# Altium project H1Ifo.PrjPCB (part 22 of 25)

## Sheet IfoEndY3.SchDoc: D1800185
size C; Engineer: Daniel Sigg; DocumentNumber: 7; Revision: 4; SheetNumber: 7; SheetTotal: 8
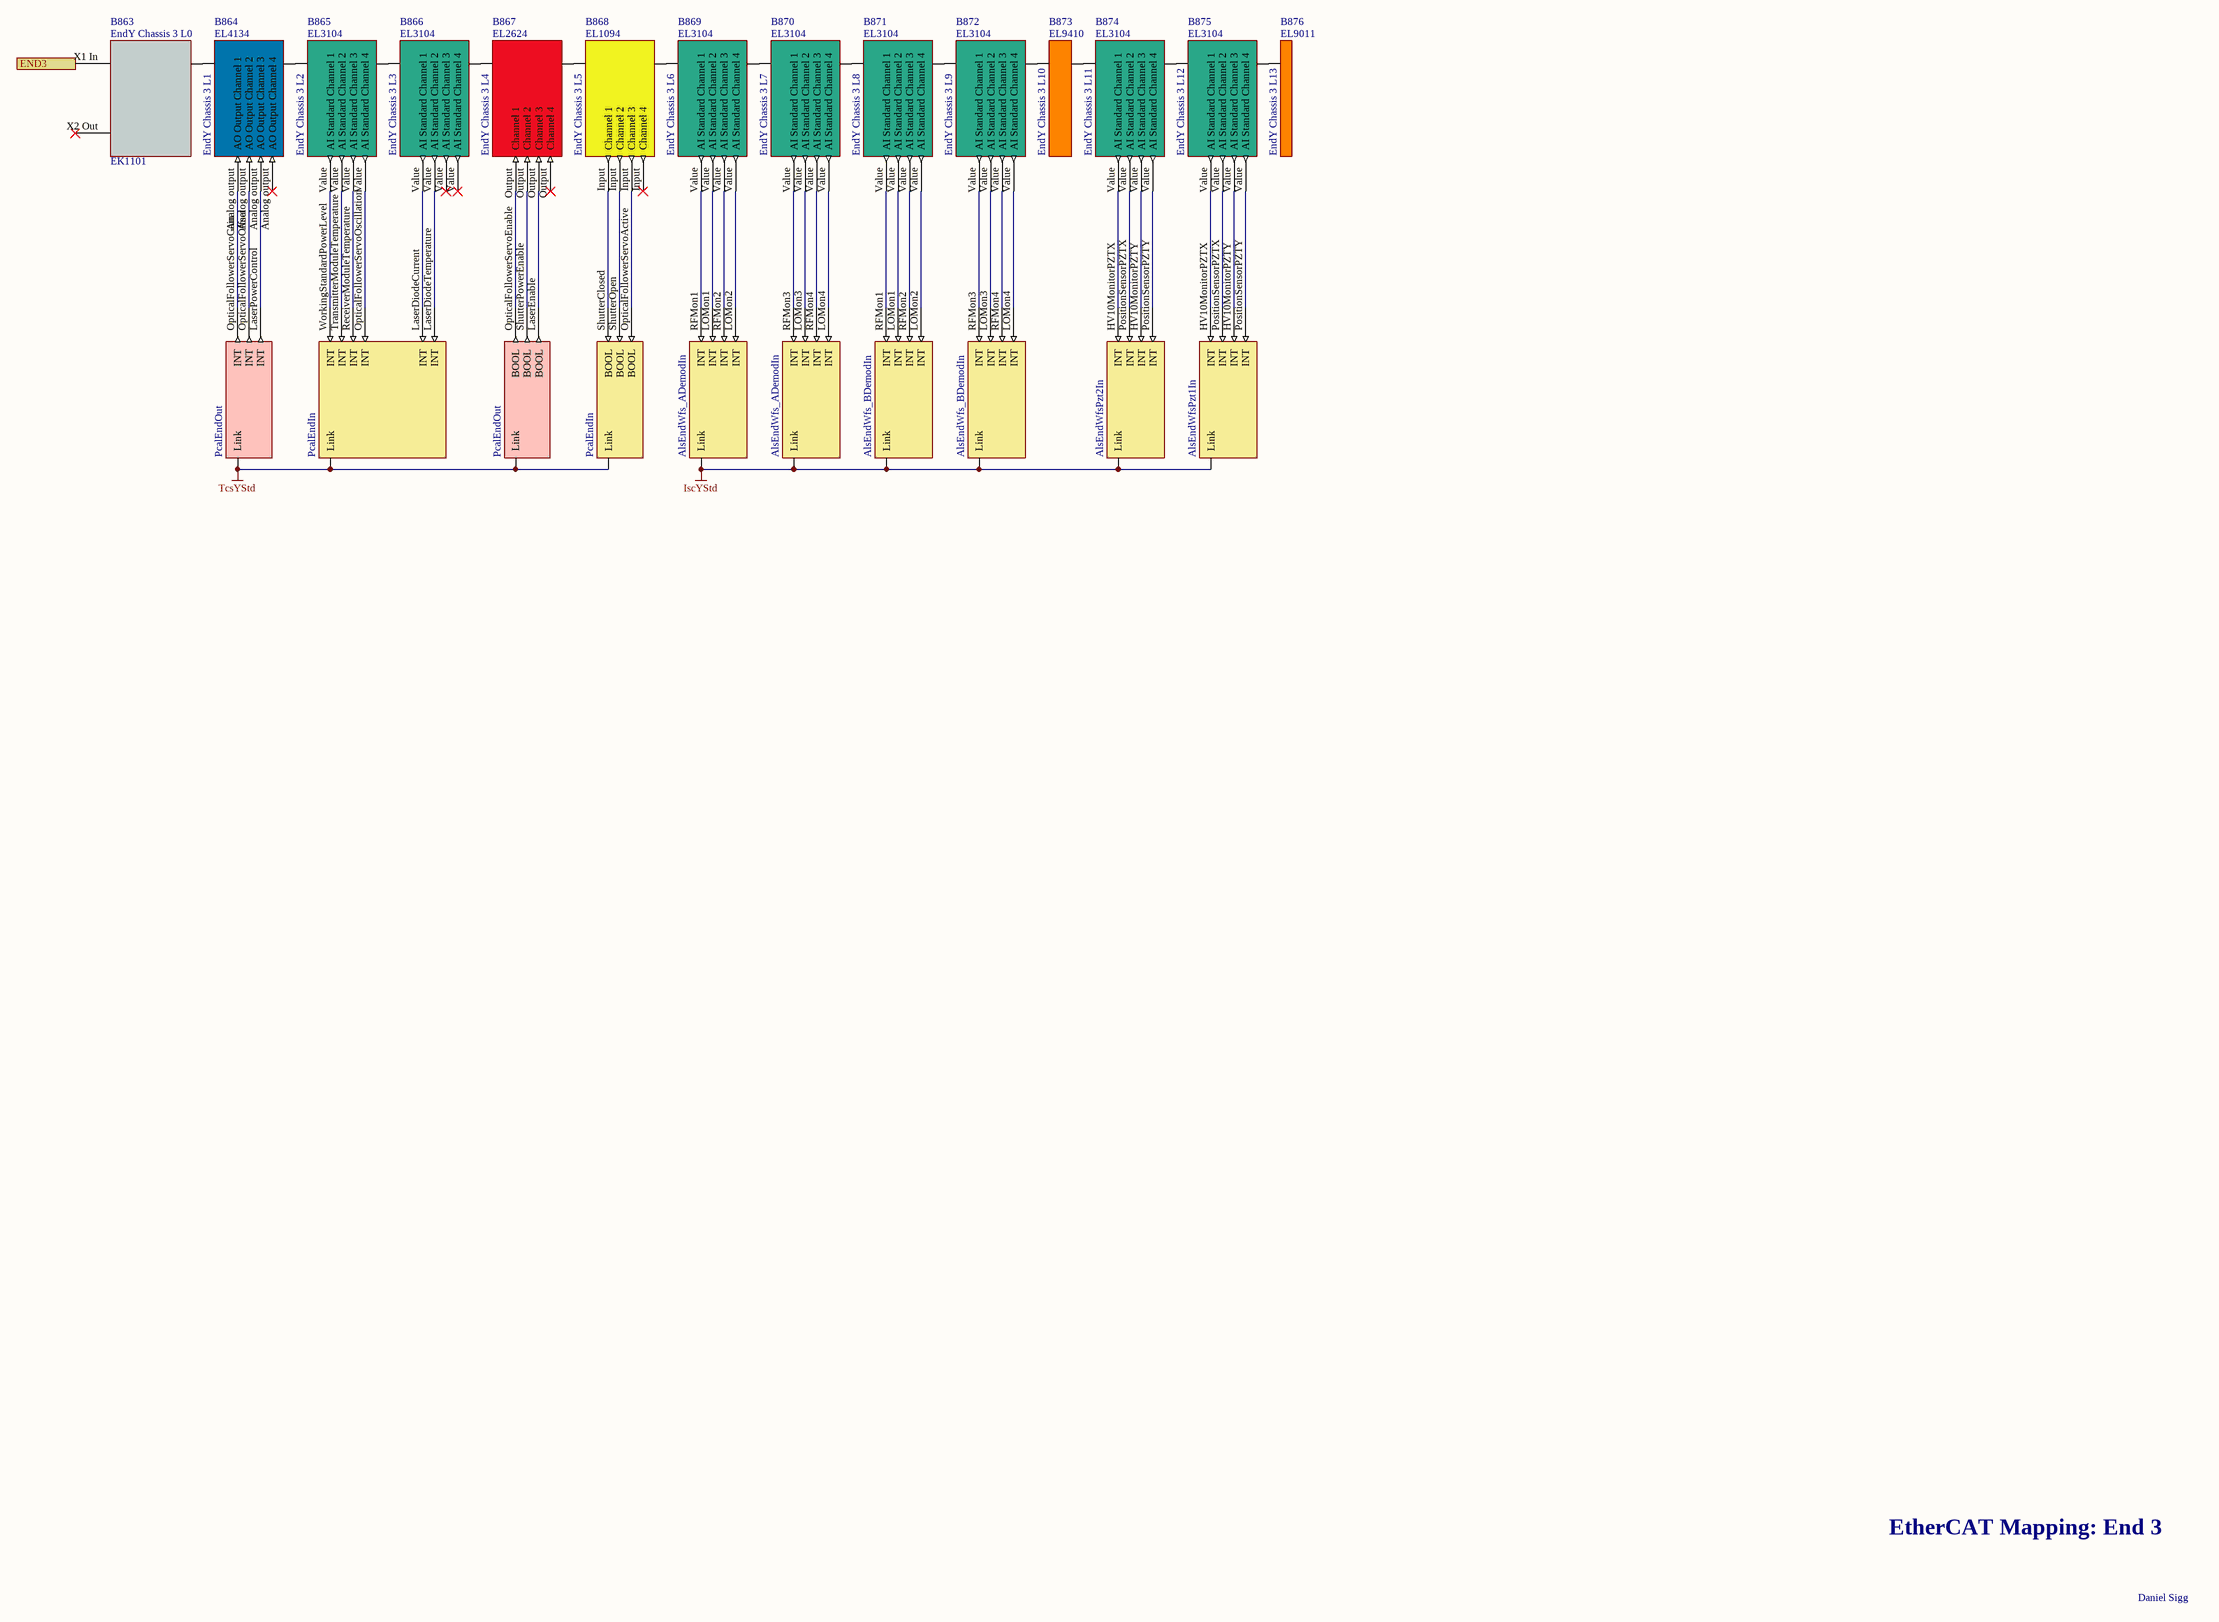
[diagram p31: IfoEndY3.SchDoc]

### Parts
B863  EndY Chassis 3 L0  Part Number: EK1101
B864  EndY Chassis 3 L1  Part Number: EL4134  (mechanical)
B865  EndY Chassis 3 L2  Part Number: EL3104  (mechanical)
B866  EndY Chassis 3 L3  Part Number: EL3104  (mechanical)
B867  EndY Chassis 3 L4  Part Number: EL2624  (mechanical)
B868  EndY Chassis 3 L5  Part Number: EL1094  (mechanical)
B869  EndY Chassis 3 L6  Part Number: EL3104  (mechanical)
B870  EndY Chassis 3 L7  Part Number: EL3104  (mechanical)
B871  EndY Chassis 3 L8  Part Number: EL3104  (mechanical)
B872  EndY Chassis 3 L9  Part Number: EL3104  (mechanical)
B873  EndY Chassis 3 L10  Part Number: EL9410  (mechanical)
B874  EndY Chassis 3 L11  Part Number: EL3104  (mechanical)
B875  EndY Chassis 3 L12  Part Number: EL3104  (mechanical)
B876  EndY Chassis 3 L13  Part Number: EL9011  (mechanical)
V678  PcalEndOut  (parts A,B of 2)  (no BOM)
V679  PcalEndIn  (parts A,B of 2)  (no BOM)
V682  AlsEndWfs_ADemodIn  (parts A,B of 2)  (no BOM)
V683  AlsEndWfs_BDemodIn  (parts A,B of 2)  (no BOM)
V684  AlsEndWfsPzt2In  (no BOM)
V685  AlsEndWfsPzt1In  (no BOM)

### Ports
END3

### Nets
IscYStd: V682.0(Link) V682.1(Link) V683.0(Link) V683.1(Link) V684.0(Link) V685.0(Link)
TcsYStd: V678.0(Link) V678.1(Link) V679.0(Link) V679.1(Link)
NetB710_X2 Out: B863.X1_In(A) ; port END3
NetB863_Ebus: B863.Ebus(B) B864.Ebus(A)
NetB864_Analog output: B864.Analog_output(AO_Output_Channel_1) V678.OpticalFollowerServoGain(INT)
NetB864_Analog output: B864.Analog_output(AO_Output_Channel_2) V678.OpticalFollowerServoOffset(INT)  [a separate net that carries the same name]
NetB864_Analog output: B864.Analog_output(AO_Output_Channel_3) V678.LaserPowerControl(INT)  [a separate net that carries the same name]
NetB864_Ebus: B864.Ebus(B) B865.Ebus(A)
NetB865_Ebus: B865.Ebus(B) B866.Ebus(A)
NetB865_Value: B865.Value(AI_Standard_Channel_1) V679.WorkingStandardPowerLevel(INT)
NetB865_Value: B865.Value(AI_Standard_Channel_2) V679.TransmitterModuleTemperature(INT)  [a separate net that carries the same name]
NetB865_Value: B865.Value(AI_Standard_Channel_3) V679.ReceiverModuleTemperature(INT)  [a separate net that carries the same name]
NetB865_Value: B865.Value(AI_Standard_Channel_4) V679.OpticalFollowerServoOscillation(INT)  [a separate net that carries the same name]
NetB866_Ebus: B866.Ebus(B) B867.Ebus(A)
NetB866_Value: B866.Value(AI_Standard_Channel_1) V679.LaserDiodeCurrent(INT)
NetB866_Value: B866.Value(AI_Standard_Channel_2) V679.LaserDiodeTemperature(INT)  [a separate net that carries the same name]
NetB867_Ebus: B867.Ebus(B) B868.Ebus(A)
NetB867_Output: B867.Output(Channel_1) V678.OpticalFollowerServoEnable(BOOL)
NetB867_Output: B867.Output(Channel_2) V678.ShutterPowerEnable(BOOL)  [a separate net that carries the same name]
NetB867_Output: B867.Output(Channel_3) V678.LaserEnable(BOOL)  [a separate net that carries the same name]
NetB868_Ebus: B868.Ebus(B) B869.Ebus(A)
NetB868_Input: B868.Input(Channel_1) V679.ShutterClosed(BOOL)
NetB868_Input: B868.Input(Channel_2) V679.ShutterOpen(BOOL)  [a separate net that carries the same name]
NetB868_Input: B868.Input(Channel_3) V679.OpticalFollowerServoActive(BOOL)  [a separate net that carries the same name]
NetB869_Ebus: B869.Ebus(B) B870.Ebus(A)
NetB869_Value: B869.Value(AI_Standard_Channel_1) V682.RFMon1(INT)
NetB869_Value: B869.Value(AI_Standard_Channel_2) V682.LOMon1(INT)  [a separate net that carries the same name]
NetB869_Value: B869.Value(AI_Standard_Channel_3) V682.RFMon2(INT)  [a separate net that carries the same name]
NetB869_Value: B869.Value(AI_Standard_Channel_4) V682.LOMon2(INT)  [a separate net that carries the same name]
NetB870_Ebus: B870.Ebus(B) B871.Ebus(A)
NetB870_Value: B870.Value(AI_Standard_Channel_1) V682.RFMon3(INT)
NetB870_Value: B870.Value(AI_Standard_Channel_2) V682.LOMon3(INT)  [a separate net that carries the same name]
NetB870_Value: B870.Value(AI_Standard_Channel_3) V682.RFMon4(INT)  [a separate net that carries the same name]
NetB870_Value: B870.Value(AI_Standard_Channel_4) V682.LOMon4(INT)  [a separate net that carries the same name]
NetB871_Ebus: B871.Ebus(B) B872.Ebus(A)
NetB871_Value: B871.Value(AI_Standard_Channel_1) V683.RFMon1(INT)
NetB871_Value: B871.Value(AI_Standard_Channel_2) V683.LOMon1(INT)  [a separate net that carries the same name]
NetB871_Value: B871.Value(AI_Standard_Channel_3) V683.RFMon2(INT)  [a separate net that carries the same name]
NetB871_Value: B871.Value(AI_Standard_Channel_4) V683.LOMon2(INT)  [a separate net that carries the same name]
NetB872_Ebus: B872.Ebus(B) B873.Ebus(A)
NetB872_Value: B872.Value(AI_Standard_Channel_1) V683.RFMon3(INT)
NetB872_Value: B872.Value(AI_Standard_Channel_2) V683.LOMon3(INT)  [a separate net that carries the same name]
NetB872_Value: B872.Value(AI_Standard_Channel_3) V683.RFMon4(INT)  [a separate net that carries the same name]
NetB872_Value: B872.Value(AI_Standard_Channel_4) V683.LOMon4(INT)  [a separate net that carries the same name]
NetB873_Ebus: B873.Ebus(B) B874.Ebus(A)
NetB874_Ebus: B874.Ebus(B) B875.Ebus(A)
NetB874_Value: B874.Value(AI_Standard_Channel_1) V684.HV10MonitorPZTX(INT)
NetB874_Value: B874.Value(AI_Standard_Channel_2) V684.PositionSensorPZTX(INT)  [a separate net that carries the same name]
NetB874_Value: B874.Value(AI_Standard_Channel_3) V684.HV10MonitorPZTY(INT)  [a separate net that carries the same name]
NetB874_Value: B874.Value(AI_Standard_Channel_4) V684.PositionSensorPZTY(INT)  [a separate net that carries the same name]
NetB875_Ebus: B875.Ebus(B) B876.Ebus(A)
NetB875_Value: B875.Value(AI_Standard_Channel_1) V685.HV10MonitorPZTX(INT)
NetB875_Value: B875.Value(AI_Standard_Channel_2) V685.PositionSensorPZTX(INT)  [a separate net that carries the same name]
NetB875_Value: B875.Value(AI_Standard_Channel_3) V685.HV10MonitorPZTY(INT)  [a separate net that carries the same name]
NetB875_Value: B875.Value(AI_Standard_Channel_4) V685.PositionSensorPZTY(INT)  [a separate net that carries the same name]

Not connected (* = marked no-connect by the designer): B863 X2 Out(C)*

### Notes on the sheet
- EtherCAT Mapping: End 3
- Daniel Sigg

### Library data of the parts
B863 = CouplerEK1101: EtherCAT Coupler; Rail: Left; BoxNextB: RTJVESXI; BoxPrev: FUNVNSJV; PortPrevFull: 1088/C; PortPrevShort: C 'X2 Out'; Fullname: TIID^End Y (EtherCAT)^EndY Link L0 (EK1501-0010)^EndY Link L6 (EK1521)^EndY Chassis 3 L0 (EK1101); BoxPorts: Junction; BoxAddr: 1101; Disabled: False
B864 = TerminalEL4134: EtherCAT Terminal EL4134 4-chn Analog Ouput; Rail: Left; BoxNextB: EDKGMHJS; BoxPrev: YFCVOVJW; PortPrevFull: 1101/B; PortPrevShort: B; Fullname: TIID^End Y (EtherCAT)^EndY Link L0 (EK1501-0010)^EndY Link L6 (EK1521)^EndY Chassis 3 L0 (EK1101)^EndY Chassis 3 L1 (EL4134); BoxAddr: 1102; Disabled: False
B865 = TerminalEL3104: EtherCAT Terminal EL3104 4-chn Analog Input; Rail: Left; BoxNextB: WPQDJUME; BoxPrev: RTJVESXI; PortPrevFull: 1102/B; PortPrevShort: B; Fullname: TIID^End Y (EtherCAT)^EndY Link L0 (EK1501-0010)^EndY Link L6 (EK1521)^EndY Chassis 3 L0 (EK1101)^EndY Chassis 3 L2 (EL3104); BoxAddr: 1103; Disabled: False
B866 = TerminalEL3104: EtherCAT Terminal EL3104 4-chn Analog Input; Rail: Left; BoxNextB: XTBTIPST; BoxPrev: EDKGMHJS; PortPrevFull: 1103/B; PortPrevShort: B; Fullname: TIID^End Y (EtherCAT)^EndY Link L0 (EK1501-0010)^EndY Link L6 (EK1521)^EndY Chassis 3 L0 (EK1101)^EndY Chassis 3 L3 (EL3104); BoxAddr: 1104; Disabled: False
B867 = TerminalEL2624: EtherCAT Terminal EL2624 4-channel relay output terminal 125 V AC/30 V DC; Rail: Left; BoxNextB: CDABDOMD; BoxPrev: WPQDJUME; PortPrevFull: 1104/B; PortPrevShort: B; Fullname: TIID^End Y (EtherCAT)^EndY Link L0 (EK1501-0010)^EndY Link L6 (EK1521)^EndY Chassis 3 L0 (EK1101)^EndY Chassis 3 L4 (EL2624); BoxAddr: 1105; Disabled: False
B868 = TerminalEL1094: EtherCAT Terminal EL1094 4-channel digital input terminal 24 V DC, switching to negative potential; Rail: Left; BoxNextB: HWOARXEL; BoxPrev: XTBTIPST; PortPrevFull: 1105/B; PortPrevShort: B; Fullname: TIID^End Y (EtherCAT)^EndY Link L0 (EK1501-0010)^EndY Link L6 (EK1521)^EndY Chassis 3 L0 (EK1101)^EndY Chassis 3 L5 (EL1094); BoxAddr: 1106; Disabled: False
B869 = TerminalEL3104: EtherCAT Terminal EL3104 4-chn Analog Input; Rail: Left; BoxNextB: FNVPWBXG; BoxPrev: CDABDOMD; PortPrevFull: 1106/B; PortPrevShort: B; Fullname: TIID^End Y (EtherCAT)^EndY Link L0 (EK1501-0010)^EndY Link L6 (EK1521)^EndY Chassis 3 L0 (EK1101)^EndY Chassis 3 L6 (EL3104); BoxAddr: 1107; Disabled: False
B870 = TerminalEL3104: EtherCAT Terminal EL3104 4-chn Analog Input; Rail: Left; BoxNextB: ICTEJMQO; BoxPrev: HWOARXEL; PortPrevFull: 1107/B; PortPrevShort: B; Fullname: TIID^End Y (EtherCAT)^EndY Link L0 (EK1501-0010)^EndY Link L6 (EK1521)^EndY Chassis 3 L0 (EK1101)^EndY Chassis 3 L7 (EL3104); BoxAddr: 1108; Disabled: False
B871 = TerminalEL3104: EtherCAT Terminal EL3104 4-chn Analog Input; Rail: Left; BoxNextB: KRHKWTDQ; BoxPrev: FNVPWBXG; PortPrevFull: 1108/B; PortPrevShort: B; Fullname: TIID^End Y (EtherCAT)^EndY Link L0 (EK1501-0010)^EndY Link L6 (EK1521)^EndY Chassis 3 L0 (EK1101)^EndY Chassis 3 L8 (EL3104); BoxAddr: 1109; Disabled: False
B872 = TerminalEL3104: EtherCAT Terminal EL3104 4-chn Analog Input; Rail: Left; BoxNextB: VRPATLRK; BoxPrev: ICTEJMQO; PortPrevFull: 1109/B; PortPrevShort: B; Fullname: TIID^End Y (EtherCAT)^EndY Link L0 (EK1501-0010)^EndY Link L6 (EK1521)^EndY Chassis 3 L0 (EK1101)^EndY Chassis 3 L9 (EL3104); BoxAddr: 1110; Disabled: False
B873 = TerminalEL9410: EtherCAT Terminal EL9410 Power; Rail: Left; BoxNextB: WQHOYDBG; BoxPrev: KRHKWTDQ; PortPrevFull: 1110/B; PortPrevShort: B; Fullname: TIID^End Y (EtherCAT)^EndY Link L0 (EK1501-0010)^EndY Link L6 (EK1521)^EndY Chassis 3 L0 (EK1101)^EndY Chassis 3 L10 (EL9410); BoxAddr: 1111; Disabled: False
B874 = TerminalEL3104: EtherCAT Terminal EL3104 4-chn Analog Input; Rail: Left; BoxNextB: WQSRVVLN; BoxPrev: VRPATLRK; PortPrevFull: 1111/B; PortPrevShort: B; Fullname: TIID^End Y (EtherCAT)^EndY Link L0 (EK1501-0010)^EndY Link L6 (EK1521)^EndY Chassis 3 L0 (EK1101)^EndY Chassis 3 L11 (EL3104); BoxAddr: 1112; Disabled: False
B875 = TerminalEL3104: EtherCAT Terminal EL3104 4-chn Analog Input; Rail: Left; BoxNextB: REASFWIS; BoxPrev: WQHOYDBG; PortPrevFull: 1112/B; PortPrevShort: B; Fullname: TIID^End Y (EtherCAT)^EndY Link L0 (EK1501-0010)^EndY Link L6 (EK1521)^EndY Chassis 3 L0 (EK1101)^EndY Chassis 3 L12 (EL3104); BoxAddr: 1113; Disabled: False
B876 = TerminalEL9011: EtherCAT Terminal EL9011 End; BoxType: TerminalPassive; Rail: Left; BoxPrev: WQSRVVLN; PortPrevShort: B; Fullname: TIID^End Y (EtherCAT)^EndY Link L0 (EK1501-0010)^EndY Link L6 (EK1521)^EndY Chassis 3 L0 (EK1101)^EndY Chassis 3 L13 (EL9011); Disabled: False
V678 = Pcal_PcalOutStruct: PcalOutStruct; BoxType: Variable; Instance: H1TcsEndY Instance; PLC: H1TcsEndY; Task: TcsEStd
V679 = Pcal_PcalInStruct: PcalInStruct; BoxType: Variable; Instance: H1TcsEndY Instance; PLC: H1TcsEndY; Task: TcsEStd
V682 V683 = Demodulator_DemodulatorQuadInStruct: DemodulatorQuadInStruct; BoxType: Variable; Instance: H1IscEndY Instance; PLC: H1IscEndY; Task: IscEStd
V684 V685 = PZTMirror_PZTMirrorInStruct: PZTMirrorInStruct; BoxType: Variable; Instance: H1IscEndY Instance; PLC: H1IscEndY; Task: IscEStd

## Sheet IfoEndXAux.SchDoc: D1800185
size C; Engineer: Daniel Sigg; DocumentNumber: 8; Revision: 4; SheetNumber: 8; SheetTotal: 8
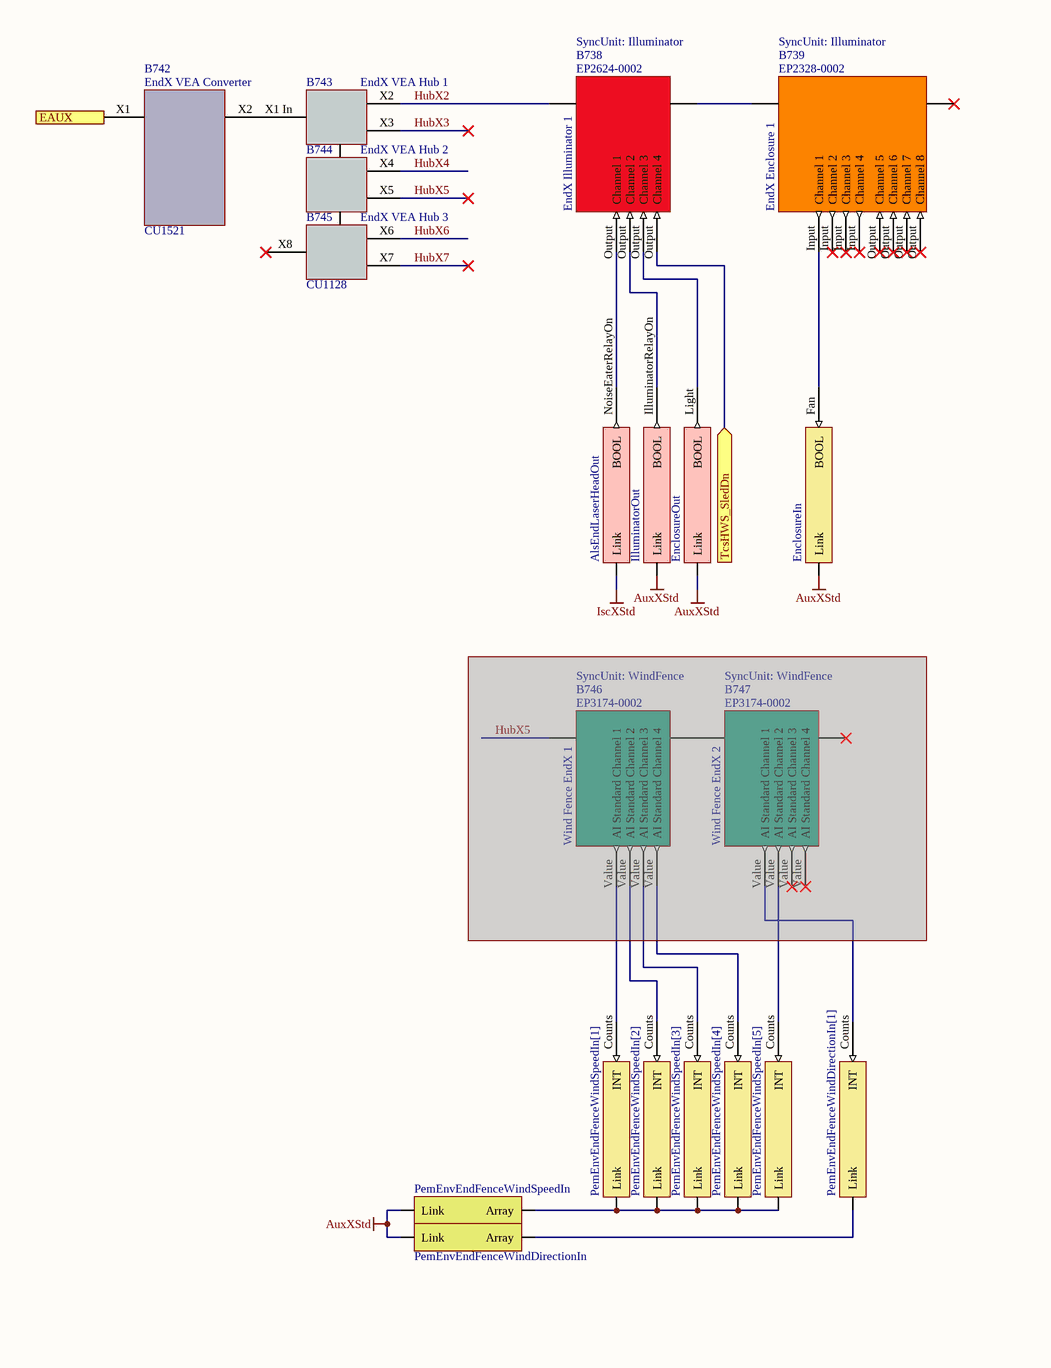
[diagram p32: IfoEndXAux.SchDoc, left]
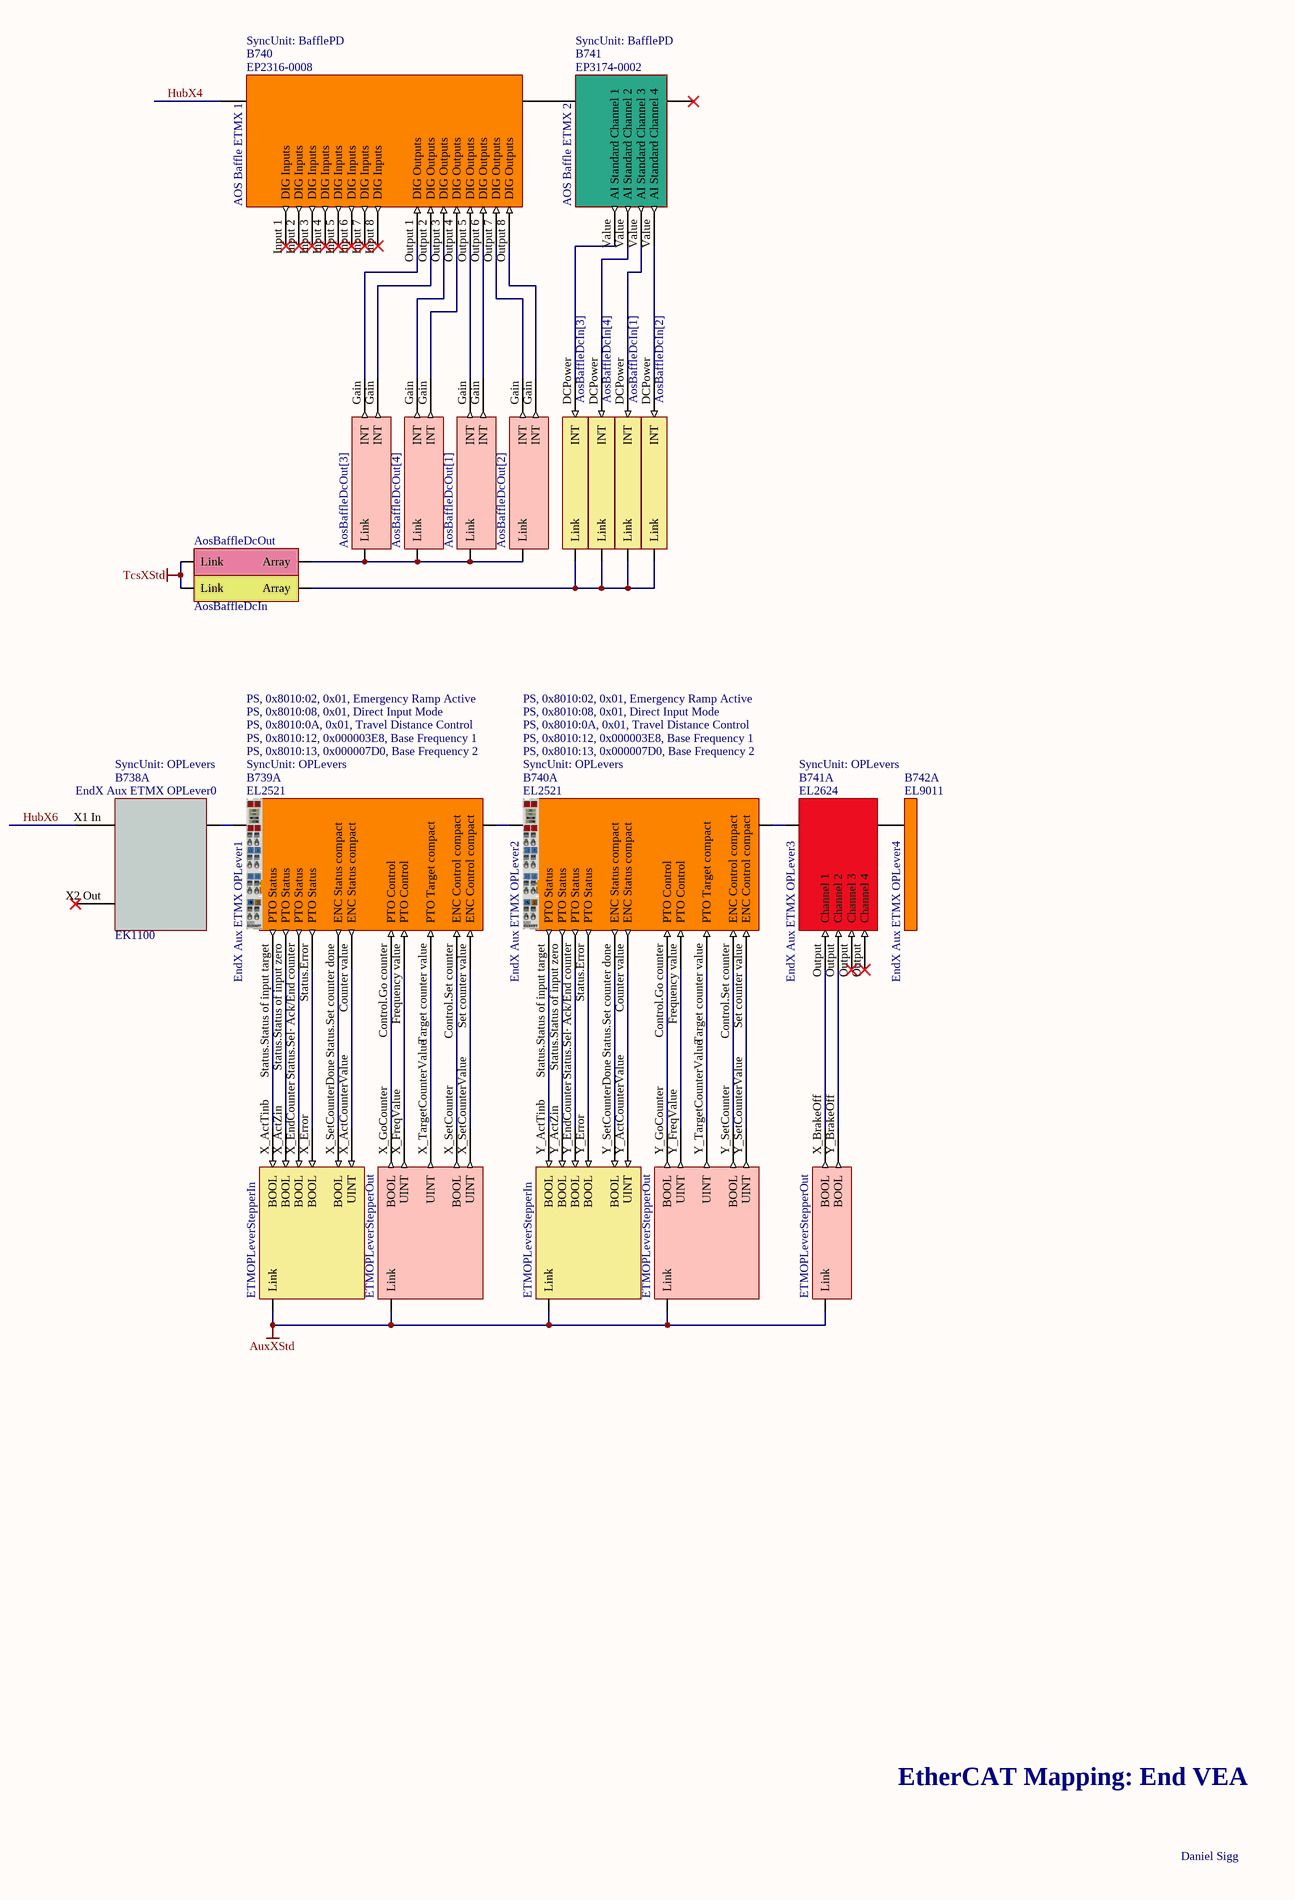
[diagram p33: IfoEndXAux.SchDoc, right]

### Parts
(Parts that share a designator on the sheet are numbered #1, #2 ... from top to bottom, then left to right.)
B738  EndX Illuminator 1  Part Number: EP2624-0002  SyncUnit: Illuminator  (mechanical)
B738A  EndX Aux ETMX OPLever0  SyncUnit: OPLevers  Part Number: EK1100  (mechanical)
B739  EndX Enclosure 1  SyncUnit: Illuminator  Part Number: EP2328-0002  (mechanical)
B739A  EndX Aux ETMX OPLever1  SyncUnit: OPLevers  Part Number: EL2521  Init0Cmd: PS, 0x8010:02, 0x01, Emergency Ramp Active  Init1Cmd: PS, 0x8010:08, 0x01, Direct Input Mode  Init2Cmd: PS, 0x8010:0A, 0x01, Travel Distance Control  Init3Cmd: PS, 0x8010:12, 0x000003E8, Base Frequency 1  Init4Cmd: PS, 0x8010:13, 0x000007D0, Base Frequency 2  (mechanical)
B740  AOS Baffle ETMX 1  Part Number: EP2316-0008  SyncUnit: BafflePD  (mechanical)
B740A  EndX Aux ETMX OPLever2  SyncUnit: OPLevers  Part Number: EL2521  Init0Cmd: PS, 0x8010:02, 0x01, Emergency Ramp Active  Init1Cmd: PS, 0x8010:08, 0x01, Direct Input Mode  Init2Cmd: PS, 0x8010:0A, 0x01, Travel Distance Control  Init3Cmd: PS, 0x8010:12, 0x000003E8, Base Frequency 1  Init4Cmd: PS, 0x8010:13, 0x000007D0, Base Frequency 2  (mechanical)
B741  AOS Baffle ETMX 2  Part Number: EP3174-0002  SyncUnit: BafflePD  (mechanical)
B741A  EndX Aux ETMX OPLever3  SyncUnit: OPLevers  Part Number: EL2624  (mechanical)
B742  EndX VEA Converter  Part Number: CU1521  (mechanical)
B742A  EndX Aux ETMX OPLever4  Part Number: EL9011  (mechanical)
B743  EndX VEA Hub 1  Part Number: CU1128  (mechanical)
B744  EndX VEA Hub 2  (mechanical)
B745  EndX VEA Hub 3  (mechanical)
B746#1  Wind Fence EndX 1  Part Number: EP3174-0002  SyncUnit: WindFence  (mechanical)  (masked out: inside a compile mask, not in the netlist)
B747#1  Wind Fence EndX 2  Part Number: EP3174-0002  SyncUnit: WindFence  (mechanical)  (masked out: inside a compile mask, not in the netlist)
V556  AlsEndLaserHeadOut  (part B of 2)  (no BOM)
V597  IlluminatorOut  (no BOM)
V597A  ETMOPLeverStepperIn  (parts A,B of 2)  (no BOM)
V598  EnclosureOut  (no BOM)
V598A  ETMOPLeverStepperOut  (parts A,B,C of 3)  (no BOM)
V599  EnclosureIn  (no BOM)
V600  AosBaffleDcOut[3]  (no BOM)
V601  AosBaffleDcOut[4]  (no BOM)
V602  AosBaffleDcOut[1]  (no BOM)
V603  AosBaffleDcOut[2]  (no BOM)
V604  AosBaffleDcIn[3]  (no BOM)
V605  AosBaffleDcIn[4]  (no BOM)
V606  AosBaffleDcIn[1]  (no BOM)
V607  AosBaffleDcIn[2]  (no BOM)
V608  AosBaffleDcOut  (no BOM)
V609  AosBaffleDcIn  (no BOM)
V610  PemEnvEndFenceWindSpeedIn[1]  (no BOM)
V611  PemEnvEndFenceWindSpeedIn[2]  (no BOM)
V612  PemEnvEndFenceWindSpeedIn[3]  (no BOM)
V613  PemEnvEndFenceWindSpeedIn[4]  (no BOM)
V614  PemEnvEndFenceWindSpeedIn[5]  (no BOM)
V615  PemEnvEndFenceWindDirectionIn[1]  (no BOM)
V616  PemEnvEndFenceWindSpeedIn  (no BOM)
V617  PemEnvEndFenceWindDirectionIn  (no BOM)

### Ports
EAUX, TcsHWS_SledDn (in)

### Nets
AuxXStd: V597.0(Link) V597A.0(Link) V597A.1(Link) V598.?1(Link) V598A.0(Link) V598A.1(Link) V598A.2(Link) V599.1(Link) V616.?1(Link) V617.?1(Link)
IscXStd: V556.1(Link)
TcsXStd: V608.?1(Link) V609.?1(Link)
HubX2: B738.?2(A) B743.X2(D)
HubX3: B743.X3(B)
HubX4: B740.?2(A) B744.X4(D)
HubX5: B744.X5(B)
HubX6: B738A.X1_In(A) B745.X6(D)
HubX7: B745.X7(B)
NetB616_X2 Out: B742.X1(A) ; port EAUX
NetB738_?1: B738.?1(B) B739.?2(A)
NetB738_Output: B738.Output(Channel_4) ; port TcsHWS_SledDn
NetB738_Output: B738.Output(Channel_1) V556.NoiseEaterRelayOn(BOOL)  [a separate net that carries the same name]
NetB738_Output: B738.Output(Channel_2) V597.IlluminatorRelayOn(BOOL)  [a separate net that carries the same name]
NetB738_Output: B738.Output(Channel_3) V598.Light(BOOL)  [a separate net that carries the same name]
NetB738A_Ebus: B738A.Ebus(B) B739A.Ebus(A)
NetB739_Input: B739.Input(Channel_1) V599.Fan(BOOL)
NetB739A_Control.Go counter: B739A.Control.Go_counter(PTO_Control) V598A.X_GoCounter(BOOL)
NetB739A_Control.Set counter: B739A.Control.Set_counter(ENC_Control_compact) V598A.X_SetCounter(BOOL)
NetB739A_Counter value: B739A.Counter_value(ENC_Status_compact) V597A.X_ActCounterValue(UINT)
NetB739A_Ebus: B739A.Ebus(B) B740A.Ebus(A)
NetB739A_Frequency value: B739A.Frequency_value(PTO_Control) V598A.X_FreqValue(UINT)
NetB739A_Set counter value: B739A.Set_counter_value(ENC_Control_compact) V598A.X_SetCounterValue(UINT)
NetB739A_Status.Error: B739A.Status.Error(PTO_Status) V597A.X_Error(BOOL)
NetB739A_Status.Sel· Ack/End counter: B739A.Status.Sel·_Ack/End_counter(PTO_Status) V597A.X_EndCounter(BOOL)
NetB739A_Status.Set counter done: B739A.Status.Set_counter_done(ENC_Status_compact) V597A.X_SetCounterDone(BOOL)
NetB739A_Status.Status of input target: B739A.Status.Status_of_input_target(PTO_Status) V597A.X_ActTinb(BOOL)
NetB739A_Status.Status of input zero: B739A.Status.Status_of_input_zero(PTO_Status) V597A.X_ActZin(BOOL)
NetB739A_Target counter value: B739A.Target_counter_value(PTO_Target_compact) V598A.X_TargetCounterValue(UINT)
NetB740_?1: B740.?1(B) B741.?2(A)
NetB740_Output 1: B740.Output_1(DIG_Outputs) V600.Gain(INT)
NetB740_Output 2: B740.Output_2(DIG_Outputs) V600.Gain(INT)
NetB740_Output 3: B740.Output_3(DIG_Outputs) V601.Gain(INT)
NetB740_Output 4: B740.Output_4(DIG_Outputs) V601.Gain(INT)
NetB740_Output 5: B740.Output_5(DIG_Outputs) V602.Gain(INT)
NetB740_Output 6: B740.Output_6(DIG_Outputs) V602.Gain(INT)
NetB740_Output 7: B740.Output_7(DIG_Outputs) V603.Gain(INT)
NetB740_Output 8: B740.Output_8(DIG_Outputs) V603.Gain(INT)
NetB740A_Control.Go counter: B740A.Control.Go_counter(PTO_Control) V598A.Y_GoCounter(BOOL)
NetB740A_Control.Set counter: B740A.Control.Set_counter(ENC_Control_compact) V598A.Y_SetCounter(BOOL)
NetB740A_Counter value: B740A.Counter_value(ENC_Status_compact) V597A.Y_ActCounterValue(UINT)
NetB740A_Ebus: B740A.Ebus(B) B741A.Ebus(A)
NetB740A_Frequency value: B740A.Frequency_value(PTO_Control) V598A.Y_FreqValue(UINT)
NetB740A_Set counter value: B740A.Set_counter_value(ENC_Control_compact) V598A.Y_SetCounterValue(UINT)
NetB740A_Status.Error: B740A.Status.Error(PTO_Status) V597A.Y_Error(BOOL)
NetB740A_Status.Sel· Ack/End counter: B740A.Status.Sel·_Ack/End_counter(PTO_Status) V597A.Y_EndCounter(BOOL)
NetB740A_Status.Set counter done: B740A.Status.Set_counter_done(ENC_Status_compact) V597A.Y_SetCounterDone(BOOL)
NetB740A_Status.Status of input target: B740A.Status.Status_of_input_target(PTO_Status) V597A.Y_ActTinb(BOOL)
NetB740A_Status.Status of input zero: B740A.Status.Status_of_input_zero(PTO_Status) V597A.Y_ActZin(BOOL)
NetB740A_Target counter value: B740A.Target_counter_value(PTO_Target_compact) V598A.Y_TargetCounterValue(UINT)
NetB741_Value: B741.Value(AI_Standard_Channel_1) V604.DCPower(INT)
NetB741_Value: B741.Value(AI_Standard_Channel_2) V605.DCPower(INT)  [a separate net that carries the same name]
NetB741_Value: B741.Value(AI_Standard_Channel_3) V606.DCPower(INT)  [a separate net that carries the same name]
NetB741_Value: B741.Value(AI_Standard_Channel_4) V607.DCPower(INT)  [a separate net that carries the same name]
NetB741A_Ebus: B741A.Ebus(B) B742A.Ebus(A)
NetB741A_Output: B741A.Output(Channel_1) V598A.X_BrakeOff(BOOL)
NetB741A_Output: B741A.Output(Channel_2) V598A.Y_BrakeOff(BOOL)  [a separate net that carries the same name]
NetB742_X2: B742.X2(B) B743.X1_In(A)
NetB743_Ebus: B743.Ebus(C) B744.Ebus(A)
NetB744_Ebus: B744.Ebus(C) B745.Ebus(A)
NetV600_0: V600.0(Link) V601.0(Link) V602.0(Link) V603.0(Link) V608.?2(Array)
NetV604_1: V604.1(Link) V605.1(Link) V606.1(Link) V607.1(Link) V609.?2(Array)
NetV610_1: V610.1(Link) V611.1(Link) V612.1(Link) V613.1(Link) V614.1(Link) V616.?2(Array)
NetV615_1: V615.1(Link) V617.?2(Array)

Not connected (* = marked no-connect by the designer): B738A X2 Out(C)*; B739 ?1(B)* Output(Channel_5)*; B740 Input 1(DIG_Inputs)* Input 2(DIG_Inputs)* Input 3(DIG_Inputs)* Input 4(DIG_Inputs)* Input 5(DIG_Inputs)* Input 6(DIG_Inputs)* Input 7(DIG_Inputs)* Input 8(DIG_Inputs)*; B741 ?1(B)*; B745 X8(C)*; V610 Counts(INT); V611 Counts(INT); V612 Counts(INT); V613 Counts(INT); V614 Counts(INT); V615 Counts(INT)

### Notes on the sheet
- EtherCAT Mapping: End VEA
- Daniel Sigg

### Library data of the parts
B738 = BoxEP2624-0002: EtherCAT Box EP2624-0002 4-channel relay output 25 V AC/30 V DC; BoxNextB: CLYTKING; BoxPrev: MHYXYRHK; PortPrevFull: 1115/D; PortPrevShort: D 'X2'; Fullname: TIID^End X (EtherCAT)^EndX Link L0 (EK1501-0010)^EndX Link L6 (EK1521)^EndX VEA Hub 1 (CU1128)^EndX Illuminator 1 (EP2624-0002); BoxAddr: 1116; Disabled: False
B738A = CouplerEK1100: EtherCAT Coupler; BoxNextB: TMZMTCVR; BoxPrev: IYIUPWIY; PortPrevFull: 1121/D; PortPrevShort: D 'X6'; Fullname: TIID^End X (EtherCAT)^EndX Link L0 (EK1501-0010)^EndX Link L6 (EK1521)^EndX VEA Hub 1 (CU1128)^EndX VEA Hub 3 (CU1128-0002)^EndX Aux ETMX OPLever0 (EK1100); BoxPorts: Junction; BoxAddr: 1122; Disabled: False
B739 = BoxEP2328-0002: EtherCAT Box EP2328-0002 4 x digital input and 4 x digital output 24 V DC; BoxPrev: MGPGGXOT; PortPrevFull: 1116/B; PortPrevShort: B; Fullname: TIID^End X (EtherCAT)^EndX Link L0 (EK1501-0010)^EndX Link L6 (EK1521)^EndX VEA Hub 1 (CU1128)^EndX Enclosure 1 (EP2328-0002); BoxAddr: 1117; Disabled: False
B739A = TerminalEL2521: EtherCAT Terminal EL2521 1-channel pulse train output, incr. enc. simulation, RS422, 50 mA; BoxNextB: RVWELLIF; BoxPrev: MMENGWJO; PortPrevFull: 1122/B; PortPrevShort: B; Fullname: TIID^End X (EtherCAT)^EndX Link L0 (EK1501-0010)^EndX Link L6 (EK1521)^EndX VEA Hub 1 (CU1128)^EndX VEA Hub 3 (CU1128-0002)^EndX Aux ETMX OPLever0 (EK1100)^EndX Aux ETMX OPLever1 (EL2521); BoxAddr: 1123; PDO Outputs: 0x1601,0x1604,0x1602; PDO Inputs: 0x1A01,0x1A02; Disabled: False
B740 = BoxEP2316-0008: EtherCAT Box EP2316-0008 8 x digital input + 8 x digital output; BoxNextB: PYNMIUIP; BoxPrev: LIKIPXHV; PortPrevFull: 1118/D; PortPrevShort: D 'X4'; Fullname: TIID^End X (EtherCAT)^EndX Link L0 (EK1501-0010)^EndX Link L6 (EK1521)^EndX VEA Hub 1 (CU1128)^EndX VEA Hub 2 (CU1128-0001)^AOS Baffle ETMX 1 (EP2316-0008); BoxAddr: 1119; Disabled: False
B740A = TerminalEL2521: EtherCAT Terminal EL2521 1-channel pulse train output, incr. enc. simulation, RS422, 50 mA; BoxNextB: LBDYYBCS; BoxPrev: TMZMTCVR; PortPrevFull: 1123/B; PortPrevShort: B; Fullname: TIID^End X (EtherCAT)^EndX Link L0 (EK1501-0010)^EndX Link L6 (EK1521)^EndX VEA Hub 1 (CU1128)^EndX VEA Hub 3 (CU1128-0002)^EndX Aux ETMX OPLever0 (EK1100)^EndX Aux ETMX OPLever2 (EL2521); BoxAddr: 1124; PDO Outputs: 0x1601,0x1604,0x1602; PDO Inputs: 0x1A01,0x1A02; Disabled: False
B741 = BoxEP3174-0002: EtherCAT Box EP3174-0002 4-channel analog input ±10 V or 0/4…20 mA, parameterisable, differential input, 16 bit; BoxPrev: BGXIVJGL; PortPrevFull: 1119/B; PortPrevShort: B; Fullname: TIID^End X (EtherCAT)^EndX Link L0 (EK1501-0010)^EndX Link L6 (EK1521)^EndX VEA Hub 1 (CU1128)^EndX VEA Hub 2 (CU1128-0001)^AOS Baffle ETMX 2 (EP3174-0002); BoxAddr: 1120; Disabled: False
B741A = TerminalEL2624: EtherCAT Terminal EL2624 4-channel relay output terminal 125 V AC/30 V DC; BoxNextB: OHMSGVAU; BoxPrev: RVWELLIF; PortPrevFull: 1124/B; PortPrevShort: B; Fullname: TIID^End X (EtherCAT)^EndX Link L0 (EK1501-0010)^EndX Link L6 (EK1521)^EndX VEA Hub 1 (CU1128)^EndX VEA Hub 3 (CU1128-0002)^EndX Aux ETMX OPLever0 (EK1100)^EndX Aux ETMX OPLever3 (EL2624); BoxAddr: 1125; Disabled: False
B742 = MediaConverterFiberToCAT5: EtherCAT Media Converter; BoxType: Box; BoxNextB: MHYXYRHK; BoxPrev: QEYXEFKI; PortPrevFull: 1007/C; PortPrevShort: C 'X2 Out'; Fullname: TIID^End X (EtherCAT)^EndX Link L0 (EK1501-0010)^EndX Link L6 (EK1521)^EndX VEA Converter (CU1521); BoxAddr: 1114; Disabled: False
B742A = TerminalEL9011: EtherCAT Terminal EL9011 End; BoxType: TerminalPassive; BoxPrev: LBDYYBCS; PortPrevShort: B; Fullname: TIID^End X (EtherCAT)^EndX Link L0 (EK1501-0010)^EndX Link L6 (EK1521)^EndX VEA Hub 1 (CU1128)^EndX VEA Hub 3 (CU1128-0002)^EndX Aux ETMX OPLever0 (EK1100)^EndX Aux ETMX OPLever4 (EL9011); Disabled: False
B743 = HubCU1128: EtherCAT Hub; BoxType: Box; BoxNextC: LIKIPXHV; BoxNextD: MGPGGXOT; BoxPrev: EQPTNBUH; PortPrevFull: 1114/B; PortPrevShort: B 'X2'; Fullname: TIID^End X (EtherCAT)^EndX Link L0 (EK1501-0010)^EndX Link L6 (EK1521)^EndX VEA Hub 1 (CU1128); BoxPorts: Junction; BoxAddr: 1115; Disabled: False
B744 = HubCU1128-B: EtherCAT Hub subpart B; Part Number: CU1128-0001; BoxType: Box; BoxNextC: IYIUPWIY; BoxNextD: BGXIVJGL; BoxPrev: MHYXYRHK; PortPrevFull: 1115/C; PortPrevShort: C; Fullname: TIID^End X (EtherCAT)^EndX Link L0 (EK1501-0010)^EndX Link L6 (EK1521)^EndX VEA Hub 1 (CU1128)^EndX VEA Hub 2 (CU1128-0001); BoxPorts: Junction; BoxAddr: 1118; Disabled: False
B745 = HubCU1128-C: EtherCAT Hub subpart C; Part Number: CU1128-0002; BoxType: Box; BoxNextD: MMENGWJO; BoxPrev: LIKIPXHV; PortPrevFull: 1118/C; Fullname: TIID^End X (EtherCAT)^EndX Link L0 (EK1501-0010)^EndX Link L6 (EK1521)^EndX VEA Hub 1 (CU1128)^EndX VEA Hub 3 (CU1128-0002); BoxPorts: Junction; BoxAddr: 1121; Disabled: False
B746#1 B747#1 = BoxEP3174-0002: EtherCAT Box EP3174-0002 4-channel analog input ±10 V or 0/4…20 mA, parameterisable, differential input, 16 bit; Disabled: False
V556 = ALSLaser_ALSLaserOutStruct: ALSLaserOutStruct; BoxType: Variable; Instance: H1IscEndX Instance; PLC: H1IscEndX; Task: IscEStd
V597 = Illuminator_IlluminatorOutStruct: IlluminatorOutStruct; BoxType: Variable; Instance: H1AuxEndX Instance; PLC: H1AuxEndX; Task: AuxEStd
V597A = OPLever_OPLeverStepperInStruct: OPLeverStepperInStruct; BoxType: Variable; Instance: H1AuxEndX Instance; PLC: H1AuxEndX; Task: AuxEStd
V598 = Enclosure_EnclosureOutStruct: EnclosureOutStruct; BoxType: Variable; Instance: H1AuxEndX Instance; PLC: H1AuxEndX; Task: AuxEStd
V598A = OPLever_OPLeverStepperOutStruct: OPLeverStepperOutStruct; BoxType: Variable; Instance: H1AuxEndX Instance; PLC: H1AuxEndX; Task: AuxEStd
V599 = Enclosure_EnclosureInStruct: EnclosureInStruct; BoxType: Variable; Instance: H1AuxEndX Instance; PLC: H1AuxEndX; Task: AuxEStd
V600-V603 = DCPower_DCPowerOutStruct: DCPowerOutStruct; BoxType: Variable; Instance: H1TcsEndX Instance; PLC: H1TcsEndX; Task: TcsEStd
V604-V607 = DCPower_DCPowerInStruct: DCPowerInStruct; BoxType: Variable; Instance: H1TcsEndX Instance; PLC: H1TcsEndX; Task: TcsEStd
V608 = ArrayAggregatorOut: Array [1..4] Of DCPowerOutStruct; Instance: H1TcsEndX Instance; PLC: H1TcsEndX; Task: TcsEStd; Lower Bound: 1; Upper Bound: 4
V609 = ArrayAggregatorIn: Array [1..4] Of DCPowerInStruct; Instance: H1TcsEndX Instance; PLC: H1TcsEndX; Task: TcsEStd; Lower Bound: 1; Upper Bound: 4
V610-V614 = WindSpeed_WindSpeedInStruct: WindSpeedInStruct; BoxType: Variable; Instance: H1AuxEndX Instance; PLC: H1AuxEndX; Task: AuxEStd
V615 = WindDirection_WindDirectionInStruct: WindDirectionInStruct; BoxType: Variable; Instance: H1AuxEndX Instance; PLC: H1AuxEndX; Task: AuxEStd
V616 = ArrayAggregatorIn: Array [1..5] Of WindSpeedInStruct; Instance: H1AuxEndX Instance; PLC: H1AuxEndX; Task: AuxEStd; Lower Bound: 1; Upper Bound: 5
V617 = ArrayAggregatorIn: Array [1..1] Of WindDirectionInStruct; Instance: H1AuxEndX Instance; PLC: H1AuxEndX; Task: AuxEStd; Lower Bound: 1

## Sheet IfoEndYAux.SchDoc: D1800185
size C; Engineer: Daniel Sigg; DocumentNumber: 8; Revision: 4; SheetNumber: 8; SheetTotal: 8
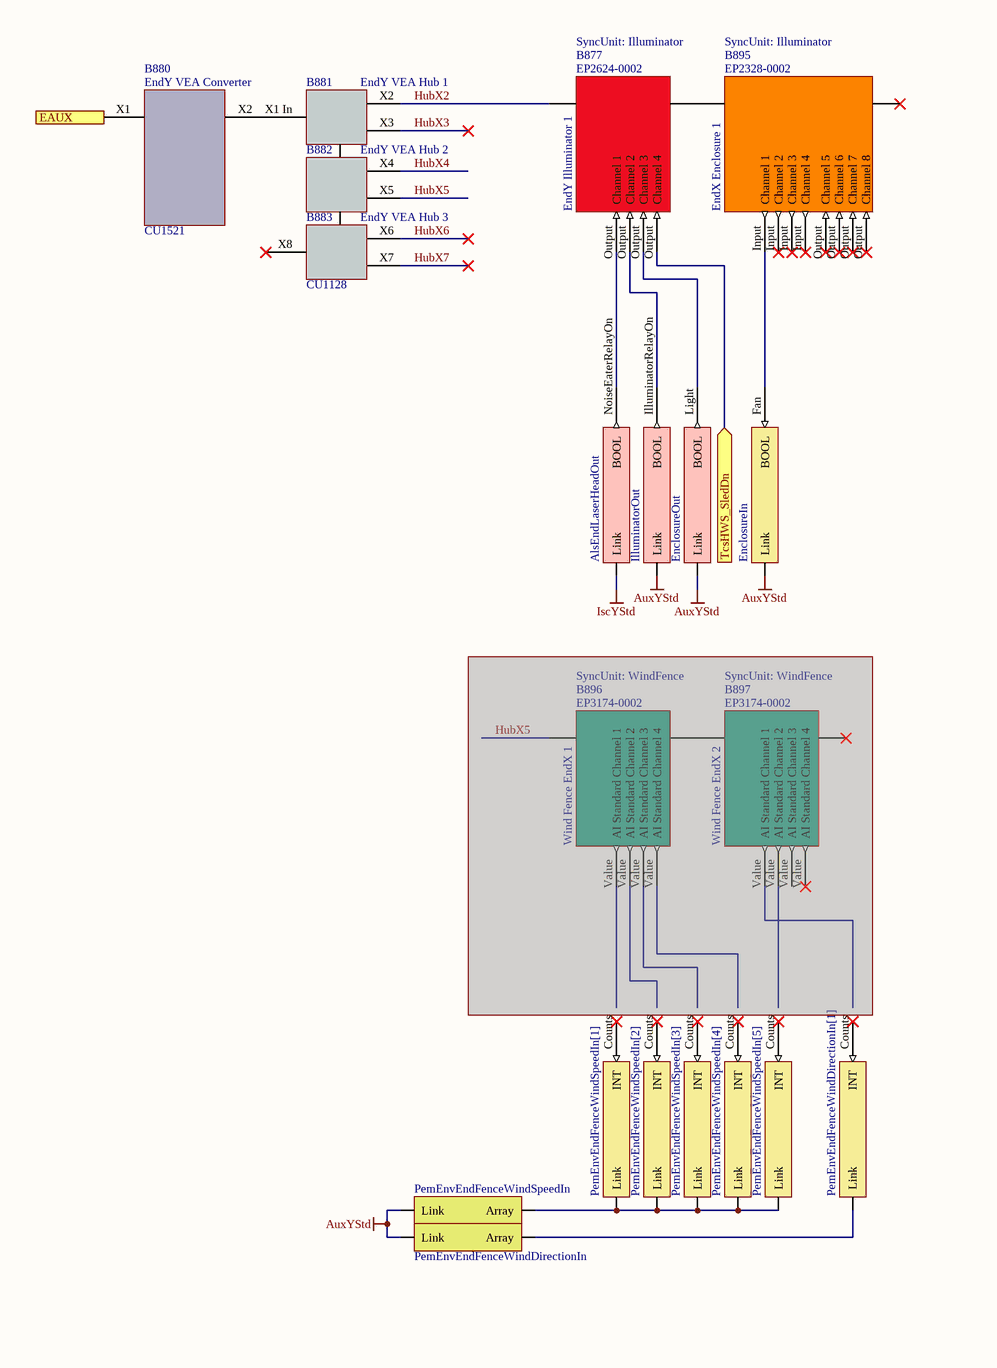
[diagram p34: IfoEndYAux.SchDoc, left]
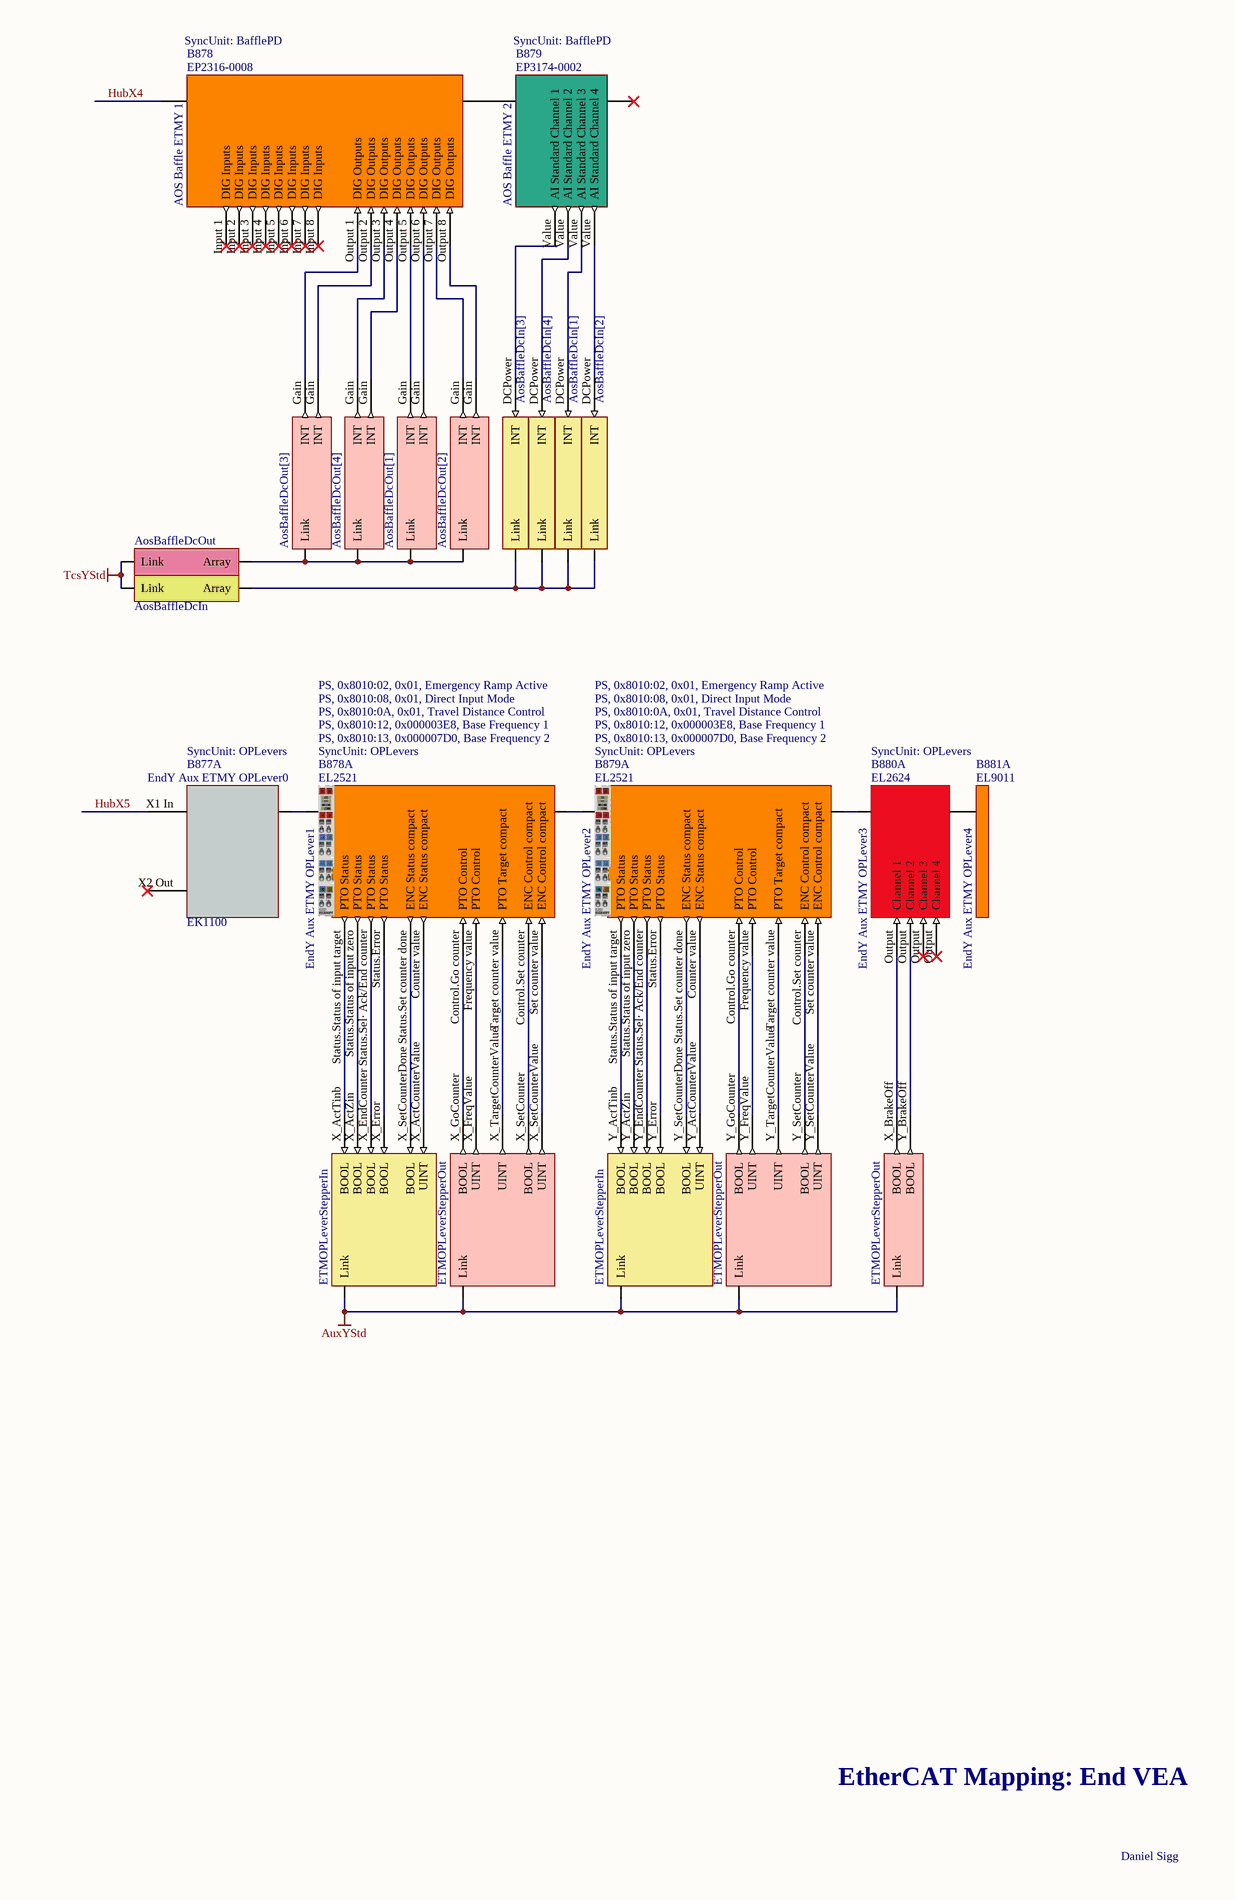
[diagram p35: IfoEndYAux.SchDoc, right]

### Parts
(Parts that share a designator on the sheet are numbered #1, #2 ... from top to bottom, then left to right.)
B877  EndY Illuminator 1  Part Number: EP2624-0002  SyncUnit: Illuminator  (mechanical)
B877A  EndY Aux ETMY OPLever0  SyncUnit: OPLevers  Part Number: EK1100  (mechanical)
B878  AOS Baffle ETMY 1  Part Number: EP2316-0008  SyncUnit: BafflePD  (mechanical)
B878A  EndY Aux ETMY OPLever1  SyncUnit: OPLevers  Part Number: EL2521  Init0Cmd: PS, 0x8010:02, 0x01, Emergency Ramp Active  Init1Cmd: PS, 0x8010:08, 0x01, Direct Input Mode  Init2Cmd: PS, 0x8010:0A, 0x01, Travel Distance Control  Init3Cmd: PS, 0x8010:12, 0x000003E8, Base Frequency 1  Init4Cmd: PS, 0x8010:13, 0x000007D0, Base Frequency 2  (mechanical)
B879  AOS Baffle ETMY 2  Part Number: EP3174-0002  SyncUnit: BafflePD  (mechanical)
B879A  EndY Aux ETMY OPLever2  SyncUnit: OPLevers  Part Number: EL2521  Init0Cmd: PS, 0x8010:02, 0x01, Emergency Ramp Active  Init1Cmd: PS, 0x8010:08, 0x01, Direct Input Mode  Init2Cmd: PS, 0x8010:0A, 0x01, Travel Distance Control  Init3Cmd: PS, 0x8010:12, 0x000003E8, Base Frequency 1  Init4Cmd: PS, 0x8010:13, 0x000007D0, Base Frequency 2  (mechanical)
B880  EndY VEA Converter  Part Number: CU1521  (mechanical)
B880A  EndY Aux ETMY OPLever3  SyncUnit: OPLevers  Part Number: EL2624  (mechanical)
B881  EndY VEA Hub 1  Part Number: CU1128  (mechanical)
B881A  EndY Aux ETMY OPLever4  Part Number: EL9011  (mechanical)
B882  EndY VEA Hub 2  (mechanical)
B883  EndY VEA Hub 3  (mechanical)
B895  EndX Enclosure 1  SyncUnit: Illuminator  Part Number: EP2328-0002  (mechanical)
B896#2  Wind Fence EndX 1  Part Number: EP3174-0002  SyncUnit: WindFence  (mechanical)  (masked out: inside a compile mask, not in the netlist)
B897#2  Wind Fence EndX 2  Part Number: EP3174-0002  SyncUnit: WindFence  (mechanical)  (masked out: inside a compile mask, not in the netlist)
V649  AlsEndLaserHeadOut  (part B of 2)  (no BOM)
V686  IlluminatorOut  (no BOM)
V686A  ETMOPLeverStepperIn  (parts A,B of 2)  (no BOM)
V687  AosBaffleDcOut[3]  (no BOM)
V687A  ETMOPLeverStepperOut  (parts A,B,C of 3)  (no BOM)
V688  AosBaffleDcOut[4]  (no BOM)
V689  AosBaffleDcOut[1]  (no BOM)
V690  AosBaffleDcOut[2]  (no BOM)
V691  AosBaffleDcIn[3]  (no BOM)
V692  AosBaffleDcIn[4]  (no BOM)
V693  AosBaffleDcIn[1]  (no BOM)
V694  AosBaffleDcIn[2]  (no BOM)
V695  AosBaffleDcOut  (no BOM)
V700  AosBaffleDcIn  (no BOM)
V707  EnclosureIn  (no BOM)
V708  PemEnvEndFenceWindSpeedIn[1]  (no BOM)
V709  PemEnvEndFenceWindSpeedIn[2]  (no BOM)
V710  PemEnvEndFenceWindSpeedIn[3]  (no BOM)
V711  PemEnvEndFenceWindSpeedIn[4]  (no BOM)
V712  PemEnvEndFenceWindSpeedIn[5]  (no BOM)
V713  PemEnvEndFenceWindDirectionIn[1]  (no BOM)
V714  PemEnvEndFenceWindSpeedIn  (no BOM)
V715  PemEnvEndFenceWindDirectionIn  (no BOM)
V716  EnclosureOut  (no BOM)

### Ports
EAUX, TcsHWS_SledDn (in)

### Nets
AuxYStd: V686.0(Link) V686A.0(Link) V686A.1(Link) V687A.0(Link) V687A.1(Link) V687A.2(Link) V707.1(Link) V714.?1(Link) V715.?1(Link) V716.?1(Link)
IscYStd: V649.1(Link)
TcsYStd: V695.?1(Link) V700.?1(Link)
HubX2: B877.?2(A) B881.X2(D)
HubX3: B881.X3(B)
HubX4: B878.?2(A) B882.X4(D)
HubX5: B877A.X1_In(A) B882.X5(B)
HubX6: B883.X6(D)
HubX7: B883.X7(B)
NetB616_X2 Out: B880.X1(A) ; port EAUX
NetB738_Output: B877.Output(Channel_4) ; port TcsHWS_SledDn
NetB877_?1: B877.?1(B) B895.?2(A)
NetB877_Output: B877.Output(Channel_1) V649.NoiseEaterRelayOn(BOOL)
NetB877_Output: B877.Output(Channel_2) V686.IlluminatorRelayOn(BOOL)  [a separate net that carries the same name]
NetB877_Output: B877.Output(Channel_3) V716.Light(BOOL)  [a separate net that carries the same name]
NetB877A_Ebus: B877A.Ebus(B) B878A.Ebus(A)
NetB878_?1: B878.?1(B) B879.?2(A)
NetB878_Output 1: B878.Output_1(DIG_Outputs) V687.Gain(INT)
NetB878_Output 2: B878.Output_2(DIG_Outputs) V687.Gain(INT)
NetB878_Output 3: B878.Output_3(DIG_Outputs) V688.Gain(INT)
NetB878_Output 4: B878.Output_4(DIG_Outputs) V688.Gain(INT)
NetB878_Output 5: B878.Output_5(DIG_Outputs) V689.Gain(INT)
NetB878_Output 6: B878.Output_6(DIG_Outputs) V689.Gain(INT)
NetB878_Output 7: B878.Output_7(DIG_Outputs) V690.Gain(INT)
NetB878_Output 8: B878.Output_8(DIG_Outputs) V690.Gain(INT)
NetB878A_Control.Go counter: B878A.Control.Go_counter(PTO_Control) V687A.X_GoCounter(BOOL)
NetB878A_Control.Set counter: B878A.Control.Set_counter(ENC_Control_compact) V687A.X_SetCounter(BOOL)
NetB878A_Counter value: B878A.Counter_value(ENC_Status_compact) V686A.X_ActCounterValue(UINT)
NetB878A_Ebus: B878A.Ebus(B) B879A.Ebus(A)
NetB878A_Frequency value: B878A.Frequency_value(PTO_Control) V687A.X_FreqValue(UINT)
NetB878A_Set counter value: B878A.Set_counter_value(ENC_Control_compact) V687A.X_SetCounterValue(UINT)
NetB878A_Status.Error: B878A.Status.Error(PTO_Status) V686A.X_Error(BOOL)
NetB878A_Status.Sel· Ack/End counter: B878A.Status.Sel·_Ack/End_counter(PTO_Status) V686A.X_EndCounter(BOOL)
NetB878A_Status.Set counter done: B878A.Status.Set_counter_done(ENC_Status_compact) V686A.X_SetCounterDone(BOOL)
NetB878A_Status.Status of input target: B878A.Status.Status_of_input_target(PTO_Status) V686A.X_ActTinb(BOOL)
NetB878A_Status.Status of input zero: B878A.Status.Status_of_input_zero(PTO_Status) V686A.X_ActZin(BOOL)
NetB878A_Target counter value: B878A.Target_counter_value(PTO_Target_compact) V687A.X_TargetCounterValue(UINT)
NetB879_Value: B879.Value(AI_Standard_Channel_1) V691.DCPower(INT)
NetB879_Value: B879.Value(AI_Standard_Channel_2) V692.DCPower(INT)  [a separate net that carries the same name]
NetB879_Value: B879.Value(AI_Standard_Channel_3) V693.DCPower(INT)  [a separate net that carries the same name]
NetB879_Value: B879.Value(AI_Standard_Channel_4) V694.DCPower(INT)  [a separate net that carries the same name]
NetB879A_Control.Go counter: B879A.Control.Go_counter(PTO_Control) V687A.Y_GoCounter(BOOL)
NetB879A_Control.Set counter: B879A.Control.Set_counter(ENC_Control_compact) V687A.Y_SetCounter(BOOL)
NetB879A_Counter value: B879A.Counter_value(ENC_Status_compact) V686A.Y_ActCounterValue(UINT)
NetB879A_Ebus: B879A.Ebus(B) B880A.Ebus(A)
NetB879A_Frequency value: B879A.Frequency_value(PTO_Control) V687A.Y_FreqValue(UINT)
NetB879A_Set counter value: B879A.Set_counter_value(ENC_Control_compact) V687A.Y_SetCounterValue(UINT)
NetB879A_Status.Error: B879A.Status.Error(PTO_Status) V686A.Y_Error(BOOL)
NetB879A_Status.Sel· Ack/End counter: B879A.Status.Sel·_Ack/End_counter(PTO_Status) V686A.Y_EndCounter(BOOL)
NetB879A_Status.Set counter done: B879A.Status.Set_counter_done(ENC_Status_compact) V686A.Y_SetCounterDone(BOOL)
NetB879A_Status.Status of input target: B879A.Status.Status_of_input_target(PTO_Status) V686A.Y_ActTinb(BOOL)
NetB879A_Status.Status of input zero: B879A.Status.Status_of_input_zero(PTO_Status) V686A.Y_ActZin(BOOL)
NetB879A_Target counter value: B879A.Target_counter_value(PTO_Target_compact) V687A.Y_TargetCounterValue(UINT)
NetB880_X2: B880.X2(B) B881.X1_In(A)
NetB880A_Ebus: B880A.Ebus(B) B881A.Ebus(A)
NetB880A_Output: B880A.Output(Channel_1) V687A.X_BrakeOff(BOOL)
NetB880A_Output: B880A.Output(Channel_2) V687A.Y_BrakeOff(BOOL)  [a separate net that carries the same name]
NetB881_Ebus: B881.Ebus(C) B882.Ebus(A)
NetB882_Ebus: B882.Ebus(C) B883.Ebus(A)
NetB895_Input: B895.Input(Channel_1) V707.Fan(BOOL)
NetV687_0: V687.0(Link) V688.0(Link) V689.0(Link) V690.0(Link) V695.?2(Array)
NetV691_1: V691.1(Link) V692.1(Link) V693.1(Link) V694.1(Link) V700.?2(Array)
NetV708_1: V708.1(Link) V709.1(Link) V710.1(Link) V711.1(Link) V712.1(Link) V714.?2(Array)
NetV713_1: V713.1(Link) V715.?2(Array)

Not connected (* = marked no-connect by the designer): B877A X2 Out(C)*; B878 Input 1(DIG_Inputs)* Input 2(DIG_Inputs)* Input 3(DIG_Inputs)* Input 4(DIG_Inputs)* Input 5(DIG_Inputs)* Input 6(DIG_Inputs)* Input 7(DIG_Inputs)* Input 8(DIG_Inputs)*; B879 ?1(B)*; B883 X8(C)*; B895 ?1(B)* Output(Channel_5)*; V708 Counts(INT)*; V709 Counts(INT)*; V710 Counts(INT)*; V711 Counts(INT)*; V712 Counts(INT)*; V713 Counts(INT)*

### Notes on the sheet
- EtherCAT Mapping: End VEA
- Daniel Sigg

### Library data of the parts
B877 = BoxEP2624-0002: EtherCAT Box EP2624-0002 4-channel relay output 25 V AC/30 V DC; BoxNextB: RHDAAVMB; BoxPrev: MEUQVVTX; PortPrevFull: 1115/D; PortPrevShort: D 'X2'; Fullname: TIID^End Y (EtherCAT)^EndY Link L0 (EK1501-0010)^EndY Link L6 (EK1521)^EndY VEA Hub 1 (CU1128)^EndY Illuminator 1 (EP2624-0002); BoxAddr: 1116; Disabled: False
B877A = CouplerEK1100: EtherCAT Coupler; BoxNextB: OTJFSRTT; BoxPrev: AODWNIGF; PortPrevFull: 1118/B; PortPrevShort: B 'X5'; Fullname: TIID^End Y (EtherCAT)^EndY Link L0 (EK1501-0010)^EndY Link L6 (EK1521)^EndY VEA Hub 1 (CU1128)^EndY VEA Hub 2 (CU1128-0001)^EndY Aux ETMY OPLever0 (EK1100); BoxPorts: Junction; BoxAddr: 1121; Disabled: False
B878 = BoxEP2316-0008: EtherCAT Box EP2316-0008 8 x digital input + 8 x digital output; BoxNextB: LGKOFLFC; BoxPrev: AODWNIGF; PortPrevFull: 1118/D; PortPrevShort: D 'X4'; Fullname: TIID^End Y (EtherCAT)^EndY Link L0 (EK1501-0010)^EndY Link L6 (EK1521)^EndY VEA Hub 1 (CU1128)^EndY VEA Hub 2 (CU1128-0001)^AOS Baffle ETMY 1 (EP2316-0008); BoxAddr: 1119; Disabled: False
B878A = TerminalEL2521: EtherCAT Terminal EL2521 1-channel pulse train output, incr. enc. simulation, RS422, 50 mA; BoxNextB: JKXDFGXR; BoxPrev: FWOESITH; PortPrevFull: 1121/B; PortPrevShort: B; Fullname: TIID^End Y (EtherCAT)^EndY Link L0 (EK1501-0010)^EndY Link L6 (EK1521)^EndY VEA Hub 1 (CU1128)^EndY VEA Hub 2 (CU1128-0001)^EndY Aux ETMY OPLever0 (EK1100)^EndY Aux ETMY OPLever1 (EL2521); BoxAddr: 1122; PDO Outputs: 0x1601,0x1604,0x1602; PDO Inputs: 0x1A01,0x1A02; Disabled: False
B879 = BoxEP3174-0002: EtherCAT Box EP3174-0002 4-channel analog input ±10 V or 0/4…20 mA, parameterisable, differential input, 16 bit; BoxPrev: XGFRIHOL; PortPrevFull: 1119/B; PortPrevShort: B; Fullname: TIID^End Y (EtherCAT)^EndY Link L0 (EK1501-0010)^EndY Link L6 (EK1521)^EndY VEA Hub 1 (CU1128)^EndY VEA Hub 2 (CU1128-0001)^AOS Baffle ETMY 2 (EP3174-0002); BoxAddr: 1120; Disabled: False
B879A = TerminalEL2521: EtherCAT Terminal EL2521 1-channel pulse train output, incr. enc. simulation, RS422, 50 mA; BoxNextB: EMQHRAPL; BoxPrev: OTJFSRTT; PortPrevFull: 1122/B; PortPrevShort: B; Fullname: TIID^End Y (EtherCAT)^EndY Link L0 (EK1501-0010)^EndY Link L6 (EK1521)^EndY VEA Hub 1 (CU1128)^EndY VEA Hub 2 (CU1128-0001)^EndY Aux ETMY OPLever0 (EK1100)^EndY Aux ETMY OPLever2 (EL2521); BoxAddr: 1123; PDO Outputs: 0x1601,0x1604,0x1602; PDO Inputs: 0x1A01,0x1A02; Disabled: False
B880 = MediaConverterFiberToCAT5: EtherCAT Media Converter; BoxType: Box; BoxNextB: MEUQVVTX; BoxPrev: NEQKDDQF; PortPrevFull: 1007/C; PortPrevShort: C 'X2 Out'; Fullname: TIID^End Y (EtherCAT)^EndY Link L0 (EK1501-0010)^EndY Link L6 (EK1521)^EndY VEA Converter (CU1521); BoxAddr: 1114; Disabled: False
B880A = TerminalEL2624: EtherCAT Terminal EL2624 4-channel relay output terminal 125 V AC/30 V DC; BoxNextB: ADYJCOAH; BoxPrev: JKXDFGXR; PortPrevFull: 1123/B; PortPrevShort: B; Fullname: TIID^End Y (EtherCAT)^EndY Link L0 (EK1501-0010)^EndY Link L6 (EK1521)^EndY VEA Hub 1 (CU1128)^EndY VEA Hub 2 (CU1128-0001)^EndY Aux ETMY OPLever0 (EK1100)^EndY Aux ETMY OPLever3 (EL2624); BoxAddr: 1124; Disabled: False
B881 = HubCU1128: EtherCAT Hub; BoxType: Box; BoxNextC: AODWNIGF; BoxNextD: AHWEXOKQ; BoxPrev: KUHNJRYY; PortPrevFull: 1114/B; PortPrevShort: B 'X2'; Fullname: TIID^End Y (EtherCAT)^EndY Link L0 (EK1501-0010)^EndY Link L6 (EK1521)^EndY VEA Hub 1 (CU1128); BoxPorts: Junction; BoxAddr: 1115; Disabled: False
B881A = TerminalEL9011: EtherCAT Terminal EL9011 End; BoxType: TerminalPassive; BoxPrev: EMQHRAPL; PortPrevShort: B; Fullname: TIID^End Y (EtherCAT)^EndY Link L0 (EK1501-0010)^EndY Link L6 (EK1521)^EndY VEA Hub 1 (CU1128)^EndY VEA Hub 2 (CU1128-0001)^EndY Aux ETMY OPLever0 (EK1100)^EndY Aux ETMY OPLever4 (EL9011); Disabled: False
B882 = HubCU1128-B: EtherCAT Hub subpart B; Part Number: CU1128-0001; BoxType: Box; BoxNextB: FWOESITH; BoxNextC: QJXOTRXP; BoxNextD: XGFRIHOL; BoxPrev: MEUQVVTX; PortPrevFull: 1115/C; PortPrevShort: C; Fullname: TIID^End Y (EtherCAT)^EndY Link L0 (EK1501-0010)^EndY Link L6 (EK1521)^EndY VEA Hub 1 (CU1128)^EndY VEA Hub 2 (CU1128-0001); BoxPorts: Junction; BoxAddr: 1118; Disabled: False
B883 = HubCU1128-C: EtherCAT Hub subpart C; Part Number: CU1128-0002; BoxType: Box; BoxPrev: AODWNIGF; PortPrevFull: 1118/C; Fullname: TIID^End Y (EtherCAT)^EndY Link L0 (EK1501-0010)^EndY Link L6 (EK1521)^EndY VEA Hub 1 (CU1128)^EndY VEA Hub 3 (CU1128-0002); BoxPorts: Junction; BoxAddr: 1125; Disabled: False
B895 = BoxEP2328-0002: EtherCAT Box EP2328-0002 4 x digital input and 4 x digital output 24 V DC; BoxPrev: AHWEXOKQ; PortPrevFull: 1116/B; PortPrevShort: B; Fullname: TIID^End Y (EtherCAT)^EndY Link L0 (EK1501-0010)^EndY Link L6 (EK1521)^EndY VEA Hub 1 (CU1128)^EndX Enclosure 1 (EP2328-0002); BoxAddr: 1117; Disabled: False
B896#2 B897#2 = BoxEP3174-0002: as B746#1 on sheet IfoEndXAux
V649 = ALSLaser_ALSLaserOutStruct: ALSLaserOutStruct; BoxType: Variable; Instance: H1IscEndY Instance; PLC: H1IscEndY; Task: IscEStd
V686 = Illuminator_IlluminatorOutStruct: IlluminatorOutStruct; BoxType: Variable; Instance: H1AuxEndY Instance; PLC: H1AuxEndY; Task: AuxEStd
V686A = OPLever_OPLeverStepperInStruct: OPLeverStepperInStruct; BoxType: Variable; Instance: H1AuxEndY Instance; PLC: H1AuxEndY; Task: AuxEStd
V687-V690 = DCPower_DCPowerOutStruct: DCPowerOutStruct; BoxType: Variable; Instance: H1TcsEndY Instance; PLC: H1TcsEndY; Task: TcsEStd
V687A = OPLever_OPLeverStepperOutStruct: OPLeverStepperOutStruct; BoxType: Variable; Instance: H1AuxEndY Instance; PLC: H1AuxEndY; Task: AuxEStd
V691-V694 = DCPower_DCPowerInStruct: DCPowerInStruct; BoxType: Variable; Instance: H1TcsEndY Instance; PLC: H1TcsEndY; Task: TcsEStd
V695 = ArrayAggregatorOut: Array [1..4] Of DCPowerOutStruct; Instance: H1TcsEndY Instance; PLC: H1TcsEndY; Task: TcsEStd; Lower Bound: 1; Upper Bound: 4
V700 = ArrayAggregatorIn: Array [1..4] Of DCPowerInStruct; Instance: H1TcsEndY Instance; PLC: H1TcsEndY; Task: TcsEStd; Lower Bound: 1; Upper Bound: 4
V707 = Enclosure_EnclosureInStruct: EnclosureInStruct; BoxType: Variable; Instance: H1AuxEndY Instance; PLC: H1AuxEndY; Task: AuxEStd
V708-V712 = WindSpeed_WindSpeedInStruct: WindSpeedInStruct; BoxType: Variable; Instance: H1AuxEndY Instance; PLC: H1AuxEndY; Task: AuxEStd
V713 = WindDirection_WindDirectionInStruct: WindDirectionInStruct; BoxType: Variable; Instance: H1AuxEndY Instance; PLC: H1AuxEndY; Task: AuxEStd
V714 = ArrayAggregatorIn: Array [1..5] Of WindSpeedInStruct; Instance: H1AuxEndY Instance; PLC: H1AuxEndY; Task: AuxEStd; Lower Bound: 1; Upper Bound: 5
V715 = ArrayAggregatorIn: Array [1..1] Of WindDirectionInStruct; Instance: H1AuxEndY Instance; PLC: H1AuxEndY; Task: AuxEStd; Lower Bound: 1
V716 = Enclosure_EnclosureOutStruct: EnclosureOutStruct; BoxType: Variable; Instance: H1AuxEndY Instance; PLC: H1AuxEndY; Task: AuxEStd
